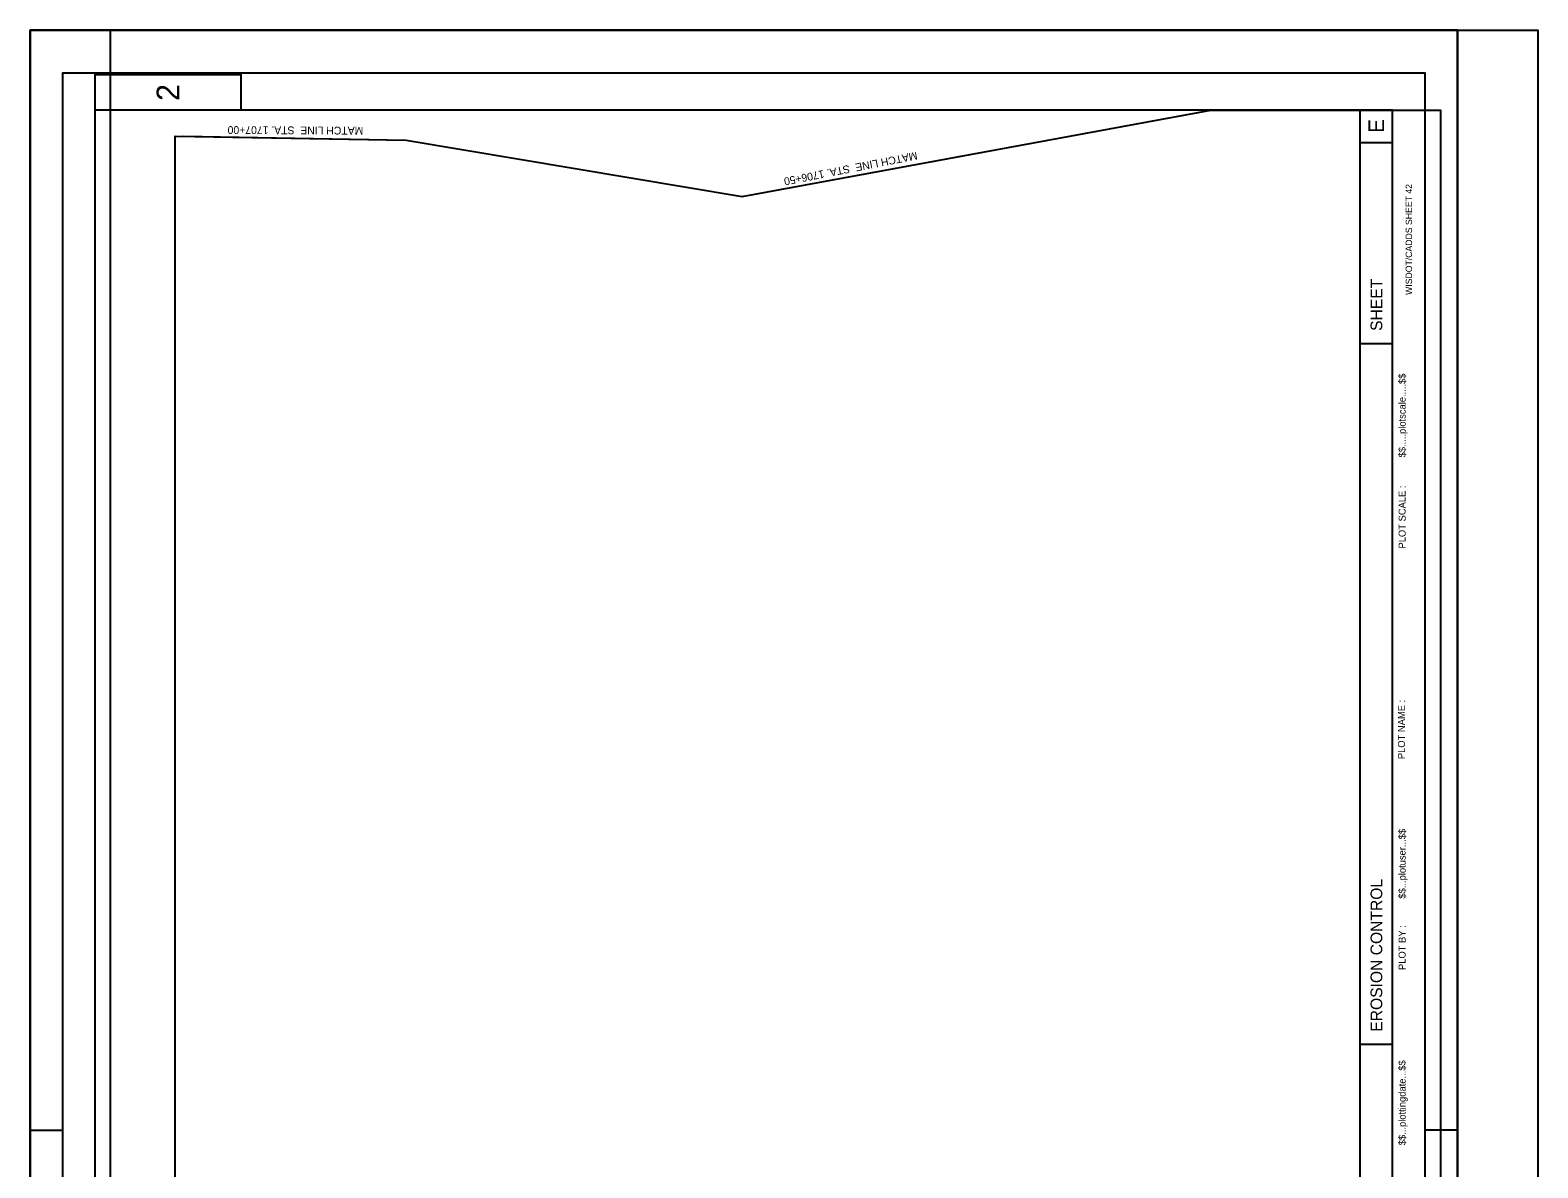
# Model space of a CAD drawing. Extents: x 361207 to 362369, y 128283 to 129983.
# Drawn here: x 361207 to 362369, y 129106 to 129983 of the extents above; entities that cross this region are included whole.
import ezdxf

# ---------------------------------------------------------------- set-up
doc = ezdxf.new("R2010")
doc.units = 0
for name, color, linetype in [('Default', 7, 'Continuous'), ('P_SHTIDX_1 [KAPUR_CADDS_LEVELS]', 7, 'Continuous'), ('P_SHTIDX_2 [KAPUR_CADDS_LEVELS]', 7, 'Continuous'), ('P_SHTIDX_3 [KAPUR_CADDS_LEVELS]', 7, 'Continuous'), ('P_TXT_Plan 3 [KAPUR_CADDS_LEVELS]', 7, 'Continuous'), ('P_TXT_Plan 4 [KAPUR_CADDS_LEVELS]', 7, 'Continuous'), ('P_TXT_Plan 4_TEXT [KAPUR_CADDS_LEVELS]', 7, 'Continuous')]:
    doc.layers.add(name, color=color, linetype=linetype)

msp = doc.modelspace()

# ---------------------------------------------------------------- linework, layer by layer
at = {"layer": 'Default'}
msp.add_lwpolyline([(361735.9, 128353.1), (361319.1, 128346.1), (361319.1, 129901.2), (361497.1, 129898), (361755.9, 129854.7), (362117.2, 129921.1), (362294.1, 129921.1), (362294.1, 128483.1), (362046.5, 128432.3), (361887.5, 128433.7)], close=True, dxfattribs=at)
msp.add_lwpolyline([(361735.9, 128353.1), (361319.1, 128346.1), (361319.1, 129901.2), (361497.1, 129898), (361755.9, 129854.7), (362117.2, 129921.1), (362294.1, 129921.1), (362294.1, 128483.1), (362046.5, 128432.3), (361887.5, 128433.7)], close=True, dxfattribs=at)
at = {"layer": 'P_SHTIDX_1 [KAPUR_CADDS_LEVELS]'}
msp.add_lwpolyline([(361269.1, 128282.8), (361269.1, 129982.8), (362369.1, 129982.8), (362369.1, 128282.8), (361269.1, 128282.8)], dxfattribs=at)
at = {"layer": 'P_SHTIDX_2 [KAPUR_CADDS_LEVELS]'}
for p, q in [((361257.2, 129982.8), (361207.2, 129982.8)), ((361207.2, 129932.8), (361207.2, 129982.8)), ((362307.2, 129982.8), (362257.2, 129982.8)), ((362307.2, 129932.8), (362307.2, 129982.8)), ((361257.2, 128346.1), (361257.2, 129921.1)), ((362257.2, 129921.1), (361257.2, 129921.1)), ((362232.2, 128346.1), (362232.2, 129921.1)), ((362257.2, 128346.1), (362257.2, 129921.1)), ((362257.2, 129896.1), (362232.2, 129896.1)), ((362257.2, 129741.1), (362232.2, 129741.1)), ((362257.2, 129201.1), (362232.2, 129201.1)), ((361207.2, 129110.3), (361207.2, 129160.3)), ((362307.2, 129110.3), (362307.2, 129160.3)), ((361207.2, 129135.3), (361232.2, 129135.3)), ((362307.2, 129135.3), (362282.2, 129135.3))]:
    msp.add_line(p, q, dxfattribs=at)
msp.add_lwpolyline([(361257.2, 129921.1), (361257.2, 129948.6), (361369.7, 129948.6), (361369.7, 129921.1)], close=True, dxfattribs=at)
at = {"layer": 'P_SHTIDX_3 [KAPUR_CADDS_LEVELS]'}
for points in [[(362307.2, 128282.8), (362307.2, 129982.8), (361207.2, 129982.8), (361207.2, 128282.8)], [(362282.2, 128294.8), (362282.2, 129949.8), (361232.2, 129949.8), (361232.2, 128294.8)]]:
    msp.add_lwpolyline(points, close=True, dxfattribs=at)
at = {"layer": 'P_TXT_Plan 4 [KAPUR_CADDS_LEVELS]'}
for p, q in [((361325.4, 129901.1), (361497.1, 129898)), ((361755.9, 129854.7), (361924.8, 129885.7))]:
    msp.add_line(p, q, dxfattribs=at)
at = {"layer": 'P_TXT_Plan 4_TEXT [KAPUR_CADDS_LEVELS]'}
msp.add_lwpolyline([(361207.2, 128282.8), (361207.2, 129982.8), (362307.2, 129982.8), (362307.2, 128282.8)], close=True, dxfattribs=at)

# ---------------------------------------------------------------- texts
at = {"layer": 'P_SHTIDX_2 [KAPUR_CADDS_LEVELS]'}
for s, height, p in [('2', 17.5, (361322.2, 129928.3)), ('E', 12, (362250.6, 129903.7)), ('WISDOT/CADDS SHEET 42', 5, (362272.2, 129778.8)), ('SHEET ', 9, (362249.2, 129751.1)), ('$$.....plotscale.....$$', 5.4, (362267.2, 129653.6)), ('PLOT SCALE : ', 5.4, (362267.2, 129583.4)), ('PLOT NAME :                      ', 5.4, (362266.7, 129421.1)), ('$$...plotuser...$$', 5.4, (362267.2, 129313.6)), ('EROSION CONTROL', 9, (362249.2, 129211.1)), ('PLOT BY :', 5.4, (362267.2, 129258.6)), ('$$...plottingdate...$$', 5.4, (362267.2, 129123.6))]:
    msp.add_text(s, height=height, rotation=90, dxfattribs=at).set_placement(p)
at = {"layer": 'P_TXT_Plan 3 [KAPUR_CADDS_LEVELS]'}
for s, rotation, p in [('MATCH LINE  STA. 1707+00', 179.6776, (361464, 129908.3)), ('MATCH LINE  STA. 1706+50', 191.1335, (361890.3, 129889.2))]:
    msp.add_text(s, height=6, rotation=rotation, dxfattribs=at).set_placement(p)

doc.saveas('drawing.dxf')
